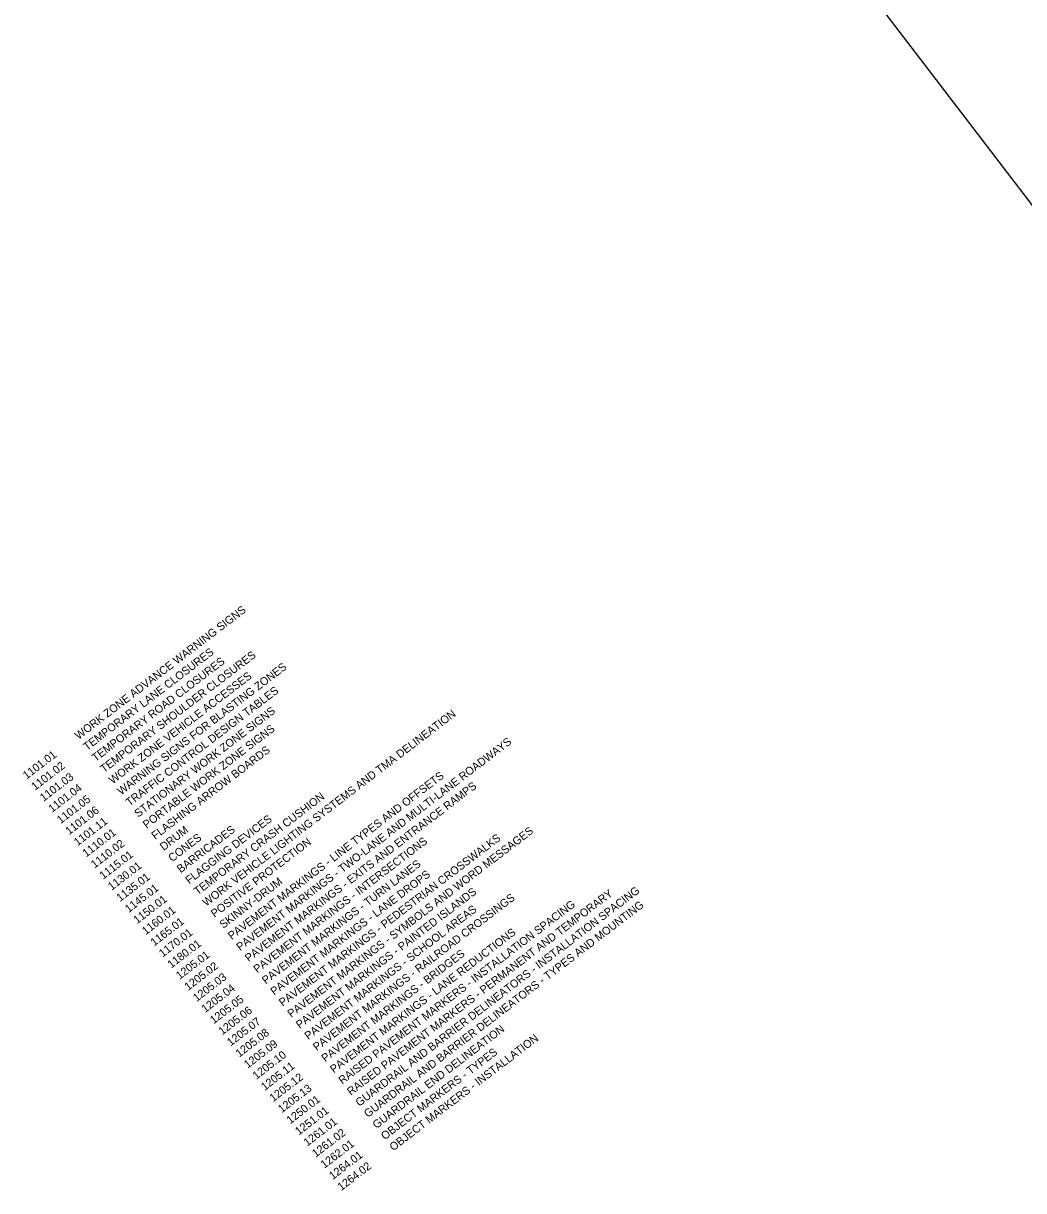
# Model space of a CAD drawing. Extents: x -606 to 2396, y -305 to 3662.
# Drawn here: x -606 to 269, y -305 to 716 of the extents above; entities that cross this region are included whole.
import ezdxf

# ---------------------------------------------------------------- set-up
doc = ezdxf.new("R2010")
doc.units = 0
doc.layers.add('DEV BORDER CELL', color=7, linetype='Continuous')
doc.layers.add('Sheet Plot Border Outside CELL', color=7, linetype='Continuous')

msp = doc.modelspace()

# ---------------------------------------------------------------- linework, layer by layer
at = {"layer": 'Sheet Plot Border Outside CELL'}
msp.add_lwpolyline([(663.6, 50.4), (2004.5, 1075.8), (1336.4, 1949.6), (-4.5, 924.2)], close=True, dxfattribs=at)

# ---------------------------------------------------------------- texts
at = {"layer": 'DEV BORDER CELL'}
for s, p in [('1101.01         WORK ZONE ADVANCE WARNING SIGNS', (-602.8, 54.1)), ('1101.02         TEMPORARY LANE CLOSURES', (-595.4, 44.4)), ('1101.04         TEMPORARY SHOULDER CLOSURES', (-580.5, 25)), ('1101.03         TEMPORARY ROAD CLOSURES', (-587.9, 34.7)), ('1101.06         WARNING SIGNS FOR BLASTING ZONES', (-565.6, 5.5)), ('1101.05         WORK ZONE VEHICLE ACCESSES', (-573, 15.2)), ('1101.11         TRAFFIC CONTROL DESIGN TABLES', (-558.2, -4.2)), ('1110.01         STATIONARY WORK ZONE SIGNS', (-550.7, -14)), ('1165.01         WORK VEHICLE LIGHTING SYSTEMS AND TMA DELINEATION', (-491.2, -91.8)), ('1110.02         PORTABLE WORK ZONE SIGNS', (-543.3, -23.7)), ('1115.01         FLASHING ARROW BOARDS', (-535.8, -33.4)), ('1205.02         PAVEMENT MARKINGS - TWO-LANE AND MULTI-LANE ROADWAYS', (-461.5, -130.7)), ('1205.01         PAVEMENT MARKINGS - LINE TYPES AND OFFSETS', (-468.9, -121)), ('1205.03         PAVEMENT MARKINGS - EXITS AND ENTRANCE RAMPS', (-454, -140.4)), ('1160.01         TEMPORARY CRASH CUSHION ', (-498.6, -82)), ('1150.01         FLAGGING DEVICES', (-506.1, -72.3)), ('1130.01         DRUM ', (-528.4, -43.1)), ('1145.01         BARRICADES', (-513.5, -62.6)), ('1205.08         PAVEMENT MARKINGS - SYMBOLS AND WORD MESSAGES', (-416.8, -189.1)), ('1135.01         CONES', (-521, -52.9)), ('1170.01         POSITIVE PROTECTION', (-483.8, -101.5)), ('1205.04         PAVEMENT MARKINGS - INTERSECTIONS', (-446.6, -150.1)), ('1205.07         PAVEMENT MARKINGS - PEDESTRIAN CROSSWALKS', (-424.3, -179.3)), ('1205.05         PAVEMENT MARKINGS - TURN LANES', (-439.1, -159.9)), ('1205.06         PAVEMENT MARKINGS - LANE DROPS', (-431.7, -169.6)), ('1180.01         SKINNY-DRUM', (-476.3, -111.2)), ('1205.09         PAVEMENT MARKINGS - PAINTED ISLANDS', (-409.4, -198.8)), ('1261.01         GUARDRAIL AND BARRIER DELINEATORS - INSTALLATION SPACING', (-357.3, -266.9)), ('1205.11         PAVEMENT MARKINGS - RAILROAD CROSSINGS', (-394.5, -218.2)), ('1251.01         RAISED PAVEMENT MARKERS - PERMANENT AND TEMPORARY ', (-364.7, -257.2)), ('1205.10         PAVEMENT MARKINGS - SCHOOL AREAS', (-401.9, -208.5)), ('1250.01         RAISED PAVEMENT MARKERS - INSTALLATION SPACING', (-372.2, -247.4)), ('1261.02         GUARDRAIL AND BARRIER DELINEATORS - TYPES AND MOUNTING ', (-349.9, -276.6)), ('1205.13         PAVEMENT MARKINGS - LANE REDUCTIONS', (-379.6, -237.7)), ('1205.12         PAVEMENT MARKINGS - BRIDGES', (-387.1, -228)), ('1262.01         GUARDRAIL END DELINEATION', (-342.4, -286.3)), ('1264.02         OBJECT MARKERS - INSTALLATION', (-327.6, -305.8)), ('1264.01         OBJECT MARKERS - TYPES', (-335, -296.1))]:
    msp.add_text(s, height=7, rotation=37.404, dxfattribs=at).set_placement(p)

doc.saveas('drawing.dxf')
